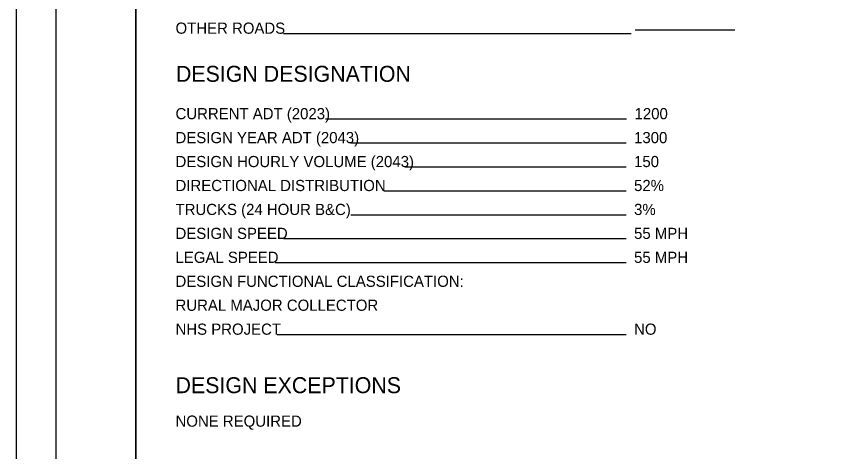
# Model space of a CAD drawing. Extents: x -1.8 to 75.7, y -2 to 25.
# Drawn here: x 41.7 to 51.85, y 7.25 to 12.71 of the extents above; entities that cross this region are included whole.
import ezdxf

# ---------------------------------------------------------------- set-up
doc = ezdxf.new("R2010")
doc.units = 0
for name, color, linetype in [('SH_Border', 7, 'Continuous'), ('SH_Cut_Line', 7, 'Continuous'), ('SH_Data', 7, 'Continuous'), ('SH_Text', 7, 'Continuous')]:
    doc.layers.add(name, color=color, linetype=linetype)

msp = doc.modelspace()

# ---------------------------------------------------------------- linework, layer by layer
at = {"layer": 'SH_Border'}
for points in [[(42.2, 23.112), (43.2, 23.112), (43.2, 2.112), (42.2, 2.112)], [(43.2, 23.112), (75.2, 23.112), (75.2, 2.112), (43.2, 2.112)]]:
    msp.add_lwpolyline(points, close=True, dxfattribs=at)
at = {"layer": 'SH_Cut_Line'}
msp.add_lwpolyline([(41.7, 1.612), (75.7, 1.612), (75.7, 23.612), (41.7, 23.612)], close=True, dxfattribs=at)
at = {"layer": 'SH_Data'}
for p, q in [((49.4, 12.489), (45.047, 12.489)), ((50.7, 12.534), (49.45, 12.534)), ((49.343, 11.418), (45.571, 11.418)), ((49.337, 11.118), (45.889, 11.118)), ((49.337, 10.818), (46.572, 10.818)), ((49.337, 10.518), (46.304, 10.518)), ((49.337, 10.218), (45.889, 10.218)), ((49.337, 9.918), (45.046, 9.918)), ((49.337, 9.618), (44.942, 9.618)), ((49.337, 8.718), (44.967, 8.718))]:
    msp.add_line(p, q, dxfattribs=at)

# ---------------------------------------------------------------- texts
msp.add_text('DESIGN DESIGNATION', height=0.2, dxfattribs=at).set_placement((43.7, 11.887))
at = {"layer": 'SH_Text'}
for s, height, p in [('OTHER ROADS', 0.14, (43.695, 12.489)), ('CURRENT ADT (2023)', 0.14, (43.695, 11.418)), ('1200', 0.14, (49.443, 11.418)), ('DESIGN YEAR ADT (2043)', 0.14, (43.695, 11.118)), ('1300', 0.14, (49.437, 11.118)), ('DESIGN HOURLY VOLUME (2043)', 0.14, (43.695, 10.818)), ('150', 0.14, (49.437, 10.818)), ('DIRECTIONAL DISTRIBUTION', 0.14, (43.695, 10.518)), ('52%', 0.14, (49.437, 10.518)), ('TRUCKS (24 HOUR B&C)', 0.14, (43.695, 10.218)), ('3%', 0.14, (49.437, 10.218)), ('DESIGN SPEED', 0.14, (43.695, 9.918)), ('55 MPH', 0.14, (49.437, 9.918)), ('LEGAL SPEED', 0.14, (43.695, 9.618)), ('55 MPH', 0.14, (49.437, 9.618)), ('DESIGN FUNCTIONAL CLASSIFICATION:', 0.14, (43.695, 9.318)), ('RURAL MAJOR COLLECTOR', 0.14, (43.695, 9.018)), ('NHS PROJECT', 0.14, (43.695, 8.718)), ('NO', 0.14, (49.437, 8.718)), ('DESIGN EXCEPTIONS', 0.2, (43.695, 7.986)), ('NONE REQUIRED', 0.14, (43.695, 7.566))]:
    msp.add_text(s, height=height, dxfattribs=at).set_placement(p)

doc.saveas('drawing.dxf')
